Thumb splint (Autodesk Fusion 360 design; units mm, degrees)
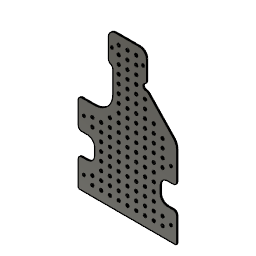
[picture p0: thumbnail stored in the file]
part number: 2025-11-24-13-59-10-673
sketch "Sketch1" plane through (0, 0, 0) normal (0, 1, 0) x axis (1, 0, 0)
  line L1 (-67.5, 0) -> (0, 0)
  line L2 (-67.5, -40) -> (-67.5, 0)
  line L3 (0, -210) -> (0, 0)
  line L4 (-45, -70) -> (-45, -40)
  line L5 (-67.5, -70) -> (-45, -70)
  line L6 (-67.5, -110) -> (-67.5, -70)
  line L7 (-20, -110) -> (-67.5, -110)
  line L8 (-20, -170) -> (-20, -110)
  line L9 (-26.25, -210) -> (-26.25, -170)
  line L10 (-26.25, -210) -> (0, -210)
  line L11 (26.25, -210) -> (0, -210)
  line L12 (26.25, -170) -> (26.25, -210)
  line L13 (67.5, -70) -> (67.5, -120)
  line L14 (67.5, 0) -> (0, 0)
  line L15 (67.5, -40) -> (67.5, 0)
  line L16 (-45, -40) -> (-67.5, -40)
  line L17 (45, -40) -> (67.5, -40)
  line L18 (45, -70) -> (45, -40)
  line L19 (67.5, -70) -> (45, -70)
  line L20 (-26.25, -170) -> (-20, -170)
  line L21 (67.5, -120) -> (20, -170)
  line L22 (20, -170) -> (26.25, -170)
  circle C1 centre (-59.5, -20) radius 1.75
  circle C2 centre (-59.5, -90) radius 1.75
  circle C3 centre (-21.25, -190) radius 1.75
  circle C4 centre (20, -170) radius 3.125
  point P1 (0, 0)
  point P2 (0, 0)
  point P6 (0, 0)
  point P20 (0, 0)
  point P3 (-67.5, 0)
  point P4 (-67.5, 0)
  point P28 (20, -170)
  point P29 (20, -170)
  point P5 (-67.5, -40)
  point P9 (-45, -40)
  point P10 (-45, -70)
  point P11 (-67.5, -70)
  point P12 (-67.5, -110)
  point P7 (0, -210)
  point P8 (-26.25, -210)
  point P16 (26.25, -210)
  point P17 (26.25, -170)
  point P15 (-26.25, -170)
  point P18 (67.5, -120)
  point P19 (67.5, -70)
  point P21 (67.5, 0)
  point P22 (67.5, -40)
  point P23 (45, -40)
  point P24 (45, -70)
  point P13 (-20, -110)
  point P14 (-20, -170)
  point P27 (-21.25, -190)
  point P26 (-59.5, -90)
  point P25 (-59.5, -20)
  coincident P1 P2
  coincident P1 P6
  perpendicular L1 L3
  vertical L4
  perpendicular L4 L5
  perpendicular L5 L6
  perpendicular L6 L7
  perpendicular L7 L8
  perpendicular L3 L10
  perpendicular L9 L10
  perpendicular L3 L11
  perpendicular L11 L12
  vertical L13
  coincident P1 P20
  perpendicular L3 L14
  perpendicular L14 L15
  perpendicular L2 L16
  perpendicular L15 L17
  perpendicular L18 L19
  perpendicular L13 L19
  coincident P3 P4
  perpendicular L1 L2
  perpendicular L8 L20
  perpendicular L4 L16
  perpendicular L12 L22
  coincident P28 P29
  dimension "d1" distance P2 P3 = 67.5 (= "( 135 / 2 ) * 1 mm")
  dimension "d2" distance P4 P5 = 40
  dimension "d4" distance P9 P10 = 30
  dimension "d7" distance P10 P11 = 22.5 (= "( ( 135 - 90 ) / 2 ) * 1 mm")
  dimension "d9" distance L3 P12 = 67.5 (= "d1")
  dimension "d10" distance P7 P8 = 26.25
  dimension "d11" distance P7 P16 = 26.25
  dimension "d12" distance P16 P17 = 40
  dimension "d13" distance P8 P15 = 40
  dimension "d14" distance L11 P18 = 90
  dimension "d15" distance L3 P18 = 67.5 (= "d1")
  dimension "d16" distance P18 P19 = 50
  dimension "d17" distance P20 P21 = 67.5
  dimension "d18" distance P21 P22 = 40
  dimension "d22" distance P23 P24 = 30 (= "d4")
  dimension "d23" distance L3 P13 = 20
  dimension "d44" distance P11 P12 = 40
  dimension "d45" distance P13 P14 = 60
  dimension "d46" diameter C1 = 3.5
  dimension "d47" diameter C2 = 3.5
  dimension "d48" diameter C3 = 3.5
  dimension "d49" distance L9 P27 = 5
  dimension "d50" distance L6 P26 = 8
  dimension "d51" distance L2 P25 = 8
  dimension "d52" distance L7 P26 = 20
  dimension "d53" distance L16 P25 = 20
  dimension "d54" distance L10 P27 = 20
  dimension "d67" distance P17 P28 = 6.25
  dimension "d74" distance P19 P24 = 22.5 (= "d7")
extrude "Extrude1" new body sketch "Sketch1" along normal blind 1.5
extrude "Extrude2" cut sketch "Sketch1" profile of C1 C2 C3 along normal blind 190.504
mirror "Mirror1" mirrorStitchTolerance 0.1
fillet "Fillet1" radius 10
fillet "Fillet2" radius 2
fillet "Fillet3" radius 10 10
fillet "Fillet4" radius 5
fillet "Fillet5" radius 25
fillet "Fillet7" radius 5 5
work_plane "WorkPlane1" AlongDistance -89.936
sketch "Sketch2" plane through (0, -89.936, 0) normal (0, 1, 0) x axis (1, 0, 0)
  line L1 (0, -210) -> (0, 0)
  circle C1 centre (-48, -13.48) radius 2
  circle C2 centre (-36, -13.48) radius 2
  circle C3 centre (-24, -13.48) radius 2
  circle C4 centre (-12, -13.48) radius 2
  circle C5 centre (0, -13.48) radius 2
  circle C6 centre (-48, -24.98) radius 2
  circle C7 centre (-36, -24.98) radius 2
  circle C8 centre (-24, -24.98) radius 2
  circle C9 centre (-12, -24.98) radius 2
  circle C10 centre (0, -24.98) radius 2
  circle C11 centre (-48, -36.48) radius 2
  circle C12 centre (-36, -36.48) radius 2
  circle C13 centre (-24, -36.48) radius 2
  circle C14 centre (-12, -36.48) radius 2
  circle C15 centre (0, -36.48) radius 2
  circle C16 centre (-48, -47.98) radius 2
  circle C17 centre (-36, -47.98) radius 2
  circle C18 centre (-24, -47.98) radius 2
  circle C19 centre (-12, -47.98) radius 2
  circle C20 centre (0, -47.98) radius 2
  circle C21 centre (12, -13.48) radius 2
  circle C22 centre (24, -13.48) radius 2
  circle C23 centre (36, -13.48) radius 2
  circle C24 centre (48, -13.48) radius 2
  circle C25 centre (12, -24.98) radius 2
  circle C26 centre (24, -24.98) radius 2
  circle C27 centre (36, -24.98) radius 2
  circle C28 centre (48, -24.98) radius 2
  circle C29 centre (12, -36.48) radius 2
  circle C30 centre (24, -36.48) radius 2
  circle C31 centre (36, -36.48) radius 2
  circle C32 centre (48, -36.48) radius 2
  circle C33 centre (12, -47.98) radius 2
  circle C34 centre (24, -47.98) radius 2
  circle C35 centre (36, -47.98) radius 2
  circle C36 centre (48, -47.98) radius 2
  circle C37 centre (-48, -59.48) radius 2
  circle C38 centre (-36, -59.48) radius 2
  circle C39 centre (-24, -59.48) radius 2
  circle C40 centre (-12, -59.48) radius 2
  circle C41 centre (0, -59.48) radius 2
  circle C42 centre (12, -59.48) radius 2
  circle C43 centre (24, -59.48) radius 2
  circle C44 centre (36, -59.48) radius 2
  circle C45 centre (48, -59.48) radius 2
  circle C46 centre (-48, -70.98) radius 2
  circle C47 centre (-36, -70.98) radius 2
  circle C48 centre (-24, -70.98) radius 2
  circle C49 centre (-12, -70.98) radius 2
  circle C50 centre (0, -70.98) radius 2
  circle C51 centre (12, -70.98) radius 2
  circle C52 centre (24, -70.98) radius 2
  circle C53 centre (36, -70.98) radius 2
  circle C54 centre (48, -70.98) radius 2
  circle C55 centre (-48, -82.48) radius 2
  circle C56 centre (-36, -82.48) radius 2
  circle C57 centre (-24, -82.48) radius 2
  circle C58 centre (-12, -82.48) radius 2
  circle C59 centre (0, -82.48) radius 2
  circle C60 centre (12, -82.48) radius 2
  circle C61 centre (24, -82.48) radius 2
  circle C62 centre (36, -82.48) radius 2
  circle C63 centre (48, -82.48) radius 2
  circle C64 centre (-48, -93.98) radius 2
  circle C65 centre (-36, -93.98) radius 2
  circle C66 centre (-24, -93.98) radius 2
  circle C67 centre (-12, -93.98) radius 2
  circle C68 centre (0, -93.98) radius 2
  circle C69 centre (12, -93.98) radius 2
  circle C70 centre (24, -93.98) radius 2
  circle C71 centre (36, -93.98) radius 2
  circle C72 centre (48, -93.98) radius 2
  circle C73 centre (-48, -105.48) radius 2
  circle C74 centre (-36, -105.48) radius 2
  circle C75 centre (-24, -105.48) radius 2
  circle C76 centre (-12, -105.48) radius 2
  circle C77 centre (0, -105.48) radius 2
  circle C78 centre (12, -105.48) radius 2
  circle C79 centre (24, -105.48) radius 2
  circle C80 centre (36, -105.48) radius 2
  circle C81 centre (48, -105.48) radius 2
  circle C82 centre (-48, -116.98) radius 2
  circle C83 centre (-36, -116.98) radius 2
  circle C84 centre (-24, -116.98) radius 2
  circle C85 centre (-12, -116.98) radius 2
  circle C86 centre (0, -116.98) radius 2
  circle C87 centre (12, -116.98) radius 2
  circle C88 centre (24, -116.98) radius 2
  circle C89 centre (36, -116.98) radius 2
  circle C90 centre (48, -116.98) radius 2
  circle C91 centre (-48, -128.48) radius 2
  circle C92 centre (-36, -128.48) radius 2
  circle C93 centre (-24, -128.48) radius 2
  circle C94 centre (-12, -128.48) radius 2
  circle C95 centre (0, -128.48) radius 2
  circle C96 centre (12, -128.48) radius 2
  circle C97 centre (24, -128.48) radius 2
  circle C98 centre (36, -128.48) radius 2
  circle C99 centre (48, -128.48) radius 2
  circle C100 centre (-48, -139.98) radius 2
  circle C101 centre (-36, -139.98) radius 2
  circle C102 centre (-24, -139.98) radius 2
  circle C103 centre (-12, -139.98) radius 2
  circle C104 centre (0, -139.98) radius 2
  circle C105 centre (12, -139.98) radius 2
  circle C106 centre (24, -139.98) radius 2
  circle C107 centre (36, -139.98) radius 2
  circle C108 centre (48, -139.98) radius 2
  circle C109 centre (-48, -151.48) radius 2
  circle C110 centre (-36, -151.48) radius 2
  circle C111 centre (-24, -151.48) radius 2
  circle C112 centre (-12, -151.48) radius 2
  circle C113 centre (0, -151.48) radius 2
  circle C114 centre (12, -151.48) radius 2
  circle C115 centre (24, -151.48) radius 2
  circle C116 centre (36, -151.48) radius 2
  circle C117 centre (48, -151.48) radius 2
  circle C118 centre (-48, -162.98) radius 2
  circle C119 centre (-36, -162.98) radius 2
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  point P6 (0, -13.48)
  coincident P6 L1
  dimension "d60" diameter C1 = 4
  dimension "d63" R-Pattern1-uDistance = 12
  dimension "d64" R-Pattern1-vDistance = -11.5
extrude "Extrude3" cut sketch "Sketch2" along normal blind 321.2595
fillet "Fillet8" radius 15 5 5
sketch "Sketch3" plane through (0, 0, 0) normal (0, -1, 0) x axis (1, 0, 0)
  line L1 (26.25, 200) -> (26.25, 171.5216)
  line L2 (-16.25, 210) -> (16.25, 210)
  line L3 (-26.25, 174.2702) -> (-26.25, 200)
  line L4 (-20, 135) -> (-20, 165)
  line L5 (-62.5, 110) -> (-45, 110)
  line L6 (-67.5, 75) -> (-67.5, 105)
  line L7 (-55, 70) -> (-62.5, 70)
  line L8 (-45, 50) -> (-45, 60)
  line L9 (-62.5, 40) -> (-55, 40)
  line L10 (-67.5, 2) -> (-67.5, 35)
  line L11 (65.5, 0) -> (-65.5, 0)
  line L12 (67.5, 35) -> (67.5, 2)
  line L13 (55, 40) -> (62.5, 40)
  line L14 (45, 60) -> (45, 50)
  line L15 (62.5, 70) -> (55, 70)
  line L16 (67.5, 114.0109) -> (67.5, 75)
  line L17 (26.3934, 163.2701) -> (63.375, 124.3421)
  arc A1 centre (21.25, 171.5216) radius 5 clockwise from (26.25, 171.5216) to (25.6342, 169.1177)
  arc A2 centre (16.25, 200) radius 10 clockwise from (16.25, 210) to (26.25, 200)
  arc A3 centre (-16.25, 200) radius 10 clockwise from (-26.25, 200) to (-16.25, 210)
  arc A4 centre (-21.25, 174.2702) radius 5 clockwise from (-23.125, 169.6351) to (-26.25, 174.2702)
  arc A5 centre (-25, 165) radius 5 clockwise from (-23.125, 169.6351) to (-20, 165)
  arc A6 centre (-45, 135) radius 25 clockwise from (-20, 135) to (-45, 110)
  arc A7 centre (-62.5, 105) radius 5 clockwise from (-67.5, 105) to (-62.5, 110)
  arc A8 centre (-62.5, 75) radius 5 clockwise from (-62.5, 70) to (-67.5, 75)
  arc A9 centre (-55, 60) radius 10 clockwise from (-55, 70) to (-45, 60)
  arc A10 centre (-55, 50) radius 10 clockwise from (-45, 50) to (-55, 40)
  arc A11 centre (-62.5, 35) radius 5 clockwise from (-67.5, 35) to (-62.5, 40)
  arc A12 centre (-65.5, 2) radius 2 clockwise from (-65.5, 0) to (-67.5, 2)
  arc A13 centre (65.5, 2) radius 2 clockwise from (67.5, 2) to (65.5, 0)
  arc A14 centre (62.5, 35) radius 5 clockwise from (62.5, 40) to (67.5, 35)
  arc A15 centre (55, 50) radius 10 clockwise from (55, 40) to (45, 50)
  arc A16 centre (55, 60) radius 10 clockwise from (45, 60) to (55, 70)
  arc A17 centre (62.5, 75) radius 5 clockwise from (67.5, 75) to (62.5, 70)
  arc A18 centre (52.5, 114.0109) radius 15 clockwise from (63.375, 124.3421) to (67.5, 114.0109)
  arc A19 centre (30.0184, 166.7138) radius 5 clockwise from (26.3934, 163.2701) to (25.6342, 169.1177)
  circle C1 centre (-59.5, 20) radius 1.75
  circle C2 centre (-59.5, 90) radius 1.75
  circle C3 centre (-21.25, 190) radius 1.75
  circle C4 centre (59.5, 20) radius 1.75
  circle C5 centre (59.5, 90) radius 1.75
  circle C6 centre (21.25, 190) radius 1.75
  circle C7 centre (36, 36.48) radius 2
  circle C8 centre (12, 197.48) radius 2
  circle C9 centre (-12, 151.48) radius 2
  circle C10 centre (-36, 47.98) radius 2
  circle C11 centre (-12, 36.48) radius 2
  circle C12 centre (0, 151.48) radius 2
  circle C13 centre (-12, 47.98) radius 2
  circle C14 centre (-12, 59.48) radius 2
  circle C15 centre (12, 185.98) radius 2
  circle C16 centre (36, 24.98) radius 2
  circle C17 centre (12, 151.48) radius 2
  circle C18 centre (24, 151.48) radius 2
  circle C19 centre (24, 139.98) radius 2
  circle C20 centre (12, 139.98) radius 2
  circle C21 centre (24, 128.48) radius 2
  circle C22 centre (-48, 24.98) radius 2
  circle C23 centre (0, 185.98) radius 2
  circle C24 centre (36, 116.98) radius 2
  circle C25 centre (12, 116.98) radius 2
  circle C26 centre (-12, 116.98) radius 2
  circle C27 centre (-12, 174.48) radius 2
  circle C28 centre (-12, 105.48) radius 2
  circle C29 centre (-12, 24.98) radius 2
  circle C30 centre (-24, 24.98) radius 2
  circle C31 centre (-12, 128.48) radius 2
  circle C32 centre (24, 36.48) radius 2
  circle C33 centre (12, 47.98) radius 2
  circle C34 centre (48, 105.48) radius 2
  circle C35 centre (0, 116.98) radius 2
  circle C36 centre (24, 70.98) radius 2
  circle C37 centre (12, 82.48) radius 2
  circle C38 centre (-24, 93.98) radius 2
  circle C39 centre (24, 59.48) radius 2
  circle C40 centre (0, 82.48) radius 2
  circle C41 centre (0, 93.98) radius 2
  circle C42 centre (-36, 70.98) radius 2
  circle C43 centre (-36, 82.48) radius 2
  circle C44 centre (-48, 82.48) radius 2
  circle C45 centre (36, 128.48) radius 2
  circle C46 centre (0, 36.48) radius 2
  circle C47 centre (0, 47.98) radius 2
  circle C48 centre (-36, 93.98) radius 2
  circle C49 centre (36, 93.98) radius 2
  circle C50 centre (48, 93.98) radius 2
  circle C51 centre (12, 105.48) radius 2
  circle C52 centre (24, 93.98) radius 2
  circle C53 centre (36, 13.48) radius 2
  circle C54 centre (12, 174.48) radius 2
  circle C55 centre (48, 13.48) radius 2
  circle C56 centre (12, 24.98) radius 2
  circle C57 centre (-12, 197.48) radius 2
  circle C58 centre (36, 47.98) radius 2
  circle C59 centre (36, 70.98) radius 2
  circle C60 centre (-24, 105.48) radius 2
  circle C61 centre (12, 93.98) radius 2
  circle C62 centre (-24, 36.48) radius 2
  circle C63 centre (0, 139.98) radius 2
  circle C64 centre (24, 13.48) radius 2
  circle C65 centre (12, 36.48) radius 2
  circle C66 centre (48, 24.98) radius 2
  circle C67 centre (-36, 59.48) radius 2
  circle C68 centre (-48, 93.98) radius 2
  circle C69 centre (-12, 82.48) radius 2
  circle C70 centre (-12, 185.98) radius 2
  circle C71 centre (12, 128.48) radius 2
  circle C72 centre (-12, 13.48) radius 2
  circle C73 centre (-24, 70.98) radius 2
  circle C74 centre (-12, 70.98) radius 2
  circle C75 centre (0, 105.48) radius 2
  circle C76 centre (0, 162.98) radius 2
  circle C77 centre (-36, 13.48) radius 2
  circle C78 centre (24, 47.98) radius 2
  circle C79 centre (12, 13.48) radius 2
  circle C80 centre (0, 128.48) radius 2
  circle C81 centre (12, 162.98) radius 2
  circle C82 centre (0, 59.48) radius 2
  circle C83 centre (36, 105.48) radius 2
  circle C84 centre (-48, 13.48) radius 2
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  point P165 (25.06, 166.0701)
  midpoint A19 P165
extrude "Extrude4" cut sketch "Sketch3" against normal blind 34.699
fillet "Fillet9" radius 5 5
